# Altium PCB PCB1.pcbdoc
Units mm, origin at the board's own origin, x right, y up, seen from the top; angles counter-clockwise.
Board outline 97 x 97 mm, 2 copper layers (Top Layer, Bottom Layer), stack 1.58 mm thick; 71 components, 12 nets, 142 pads, 0 vias.
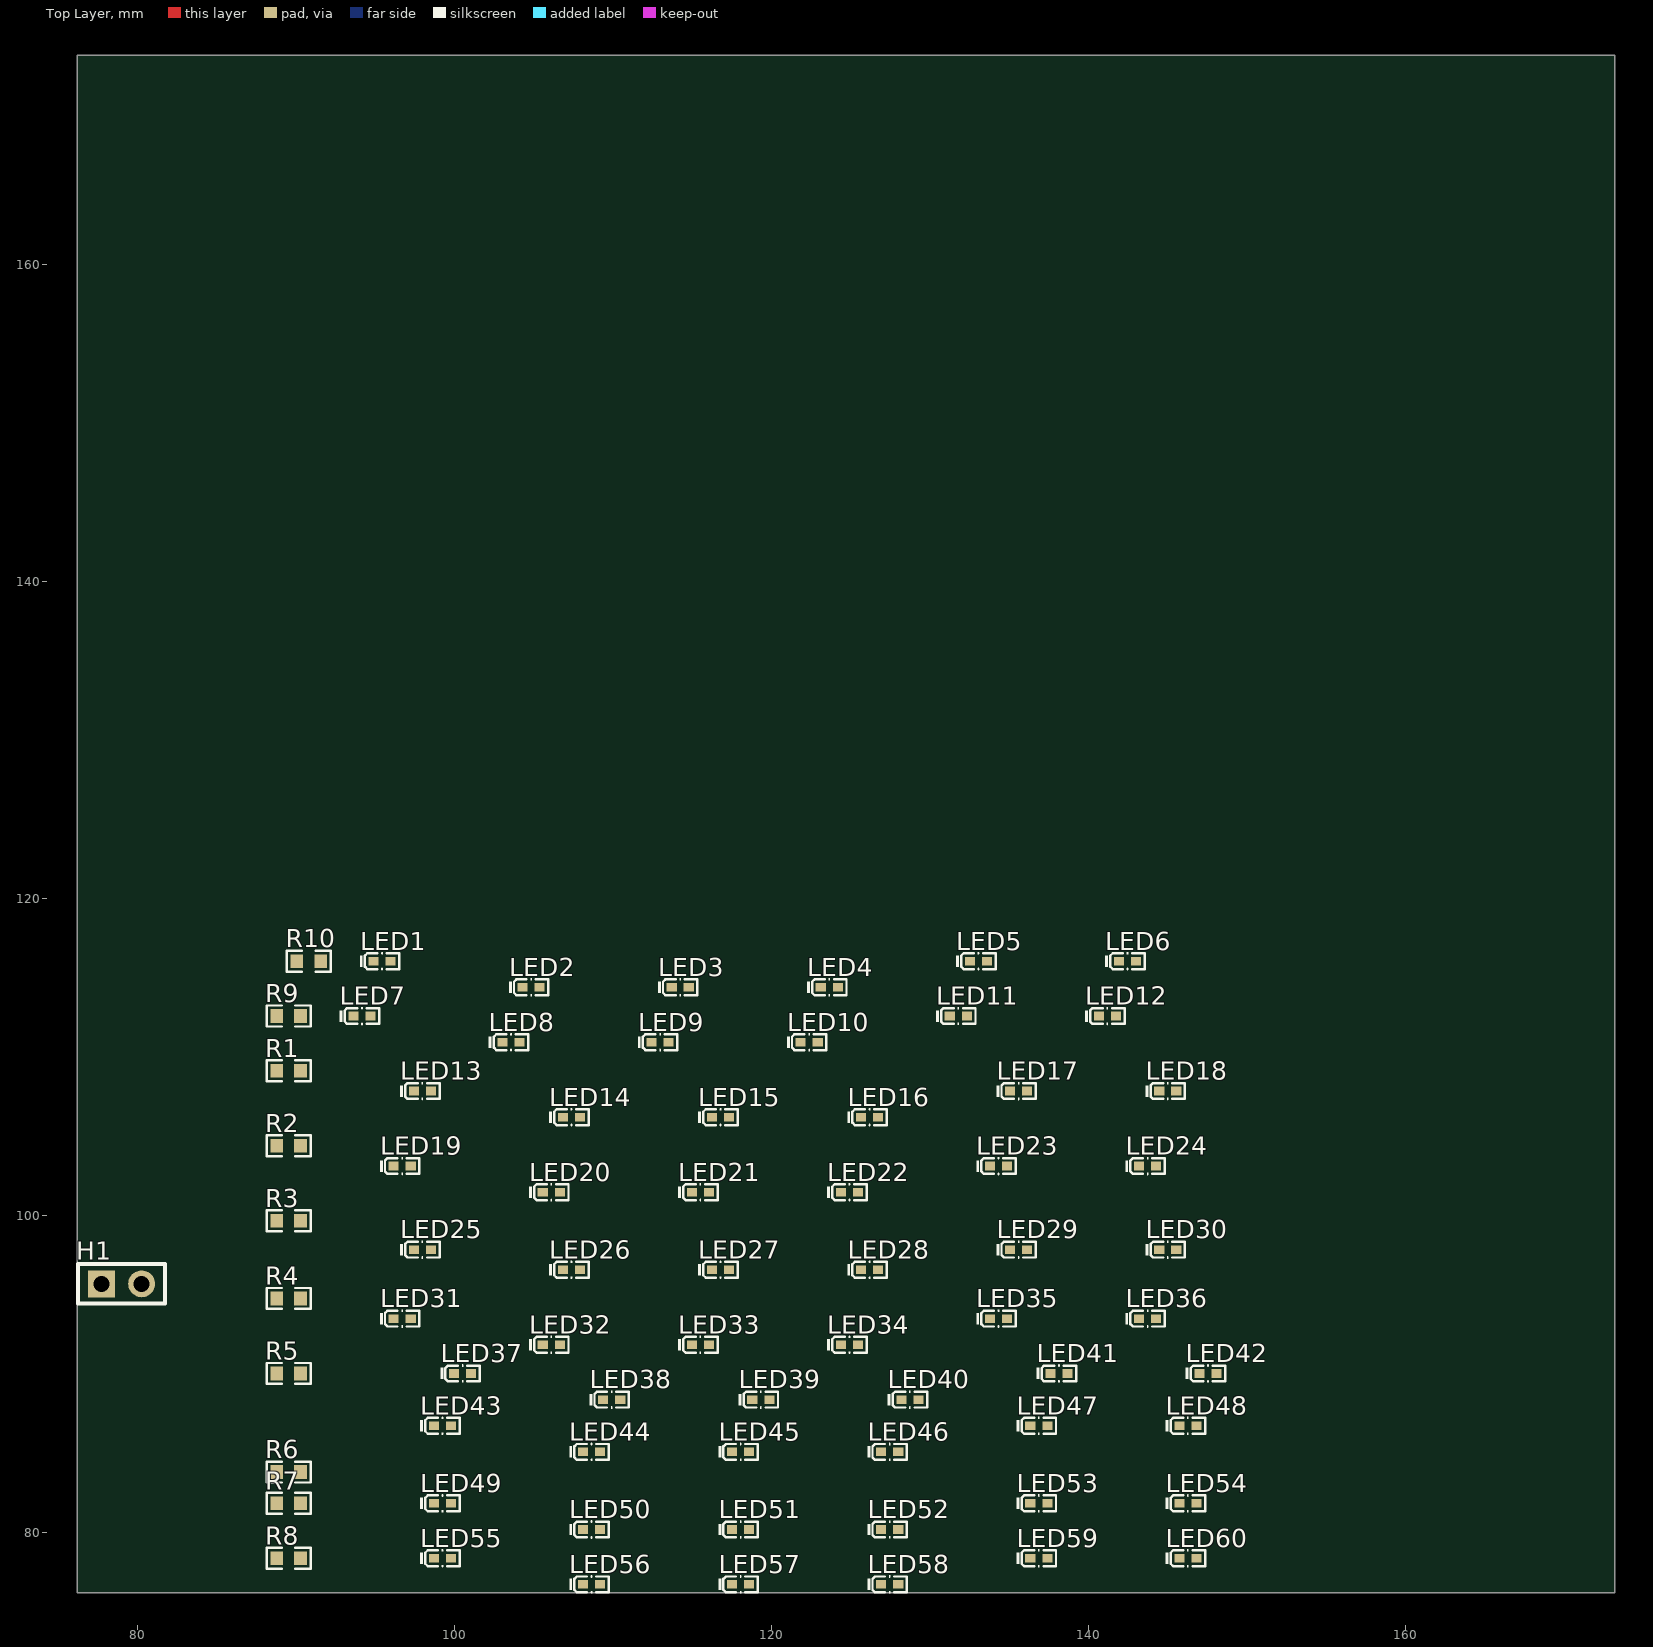
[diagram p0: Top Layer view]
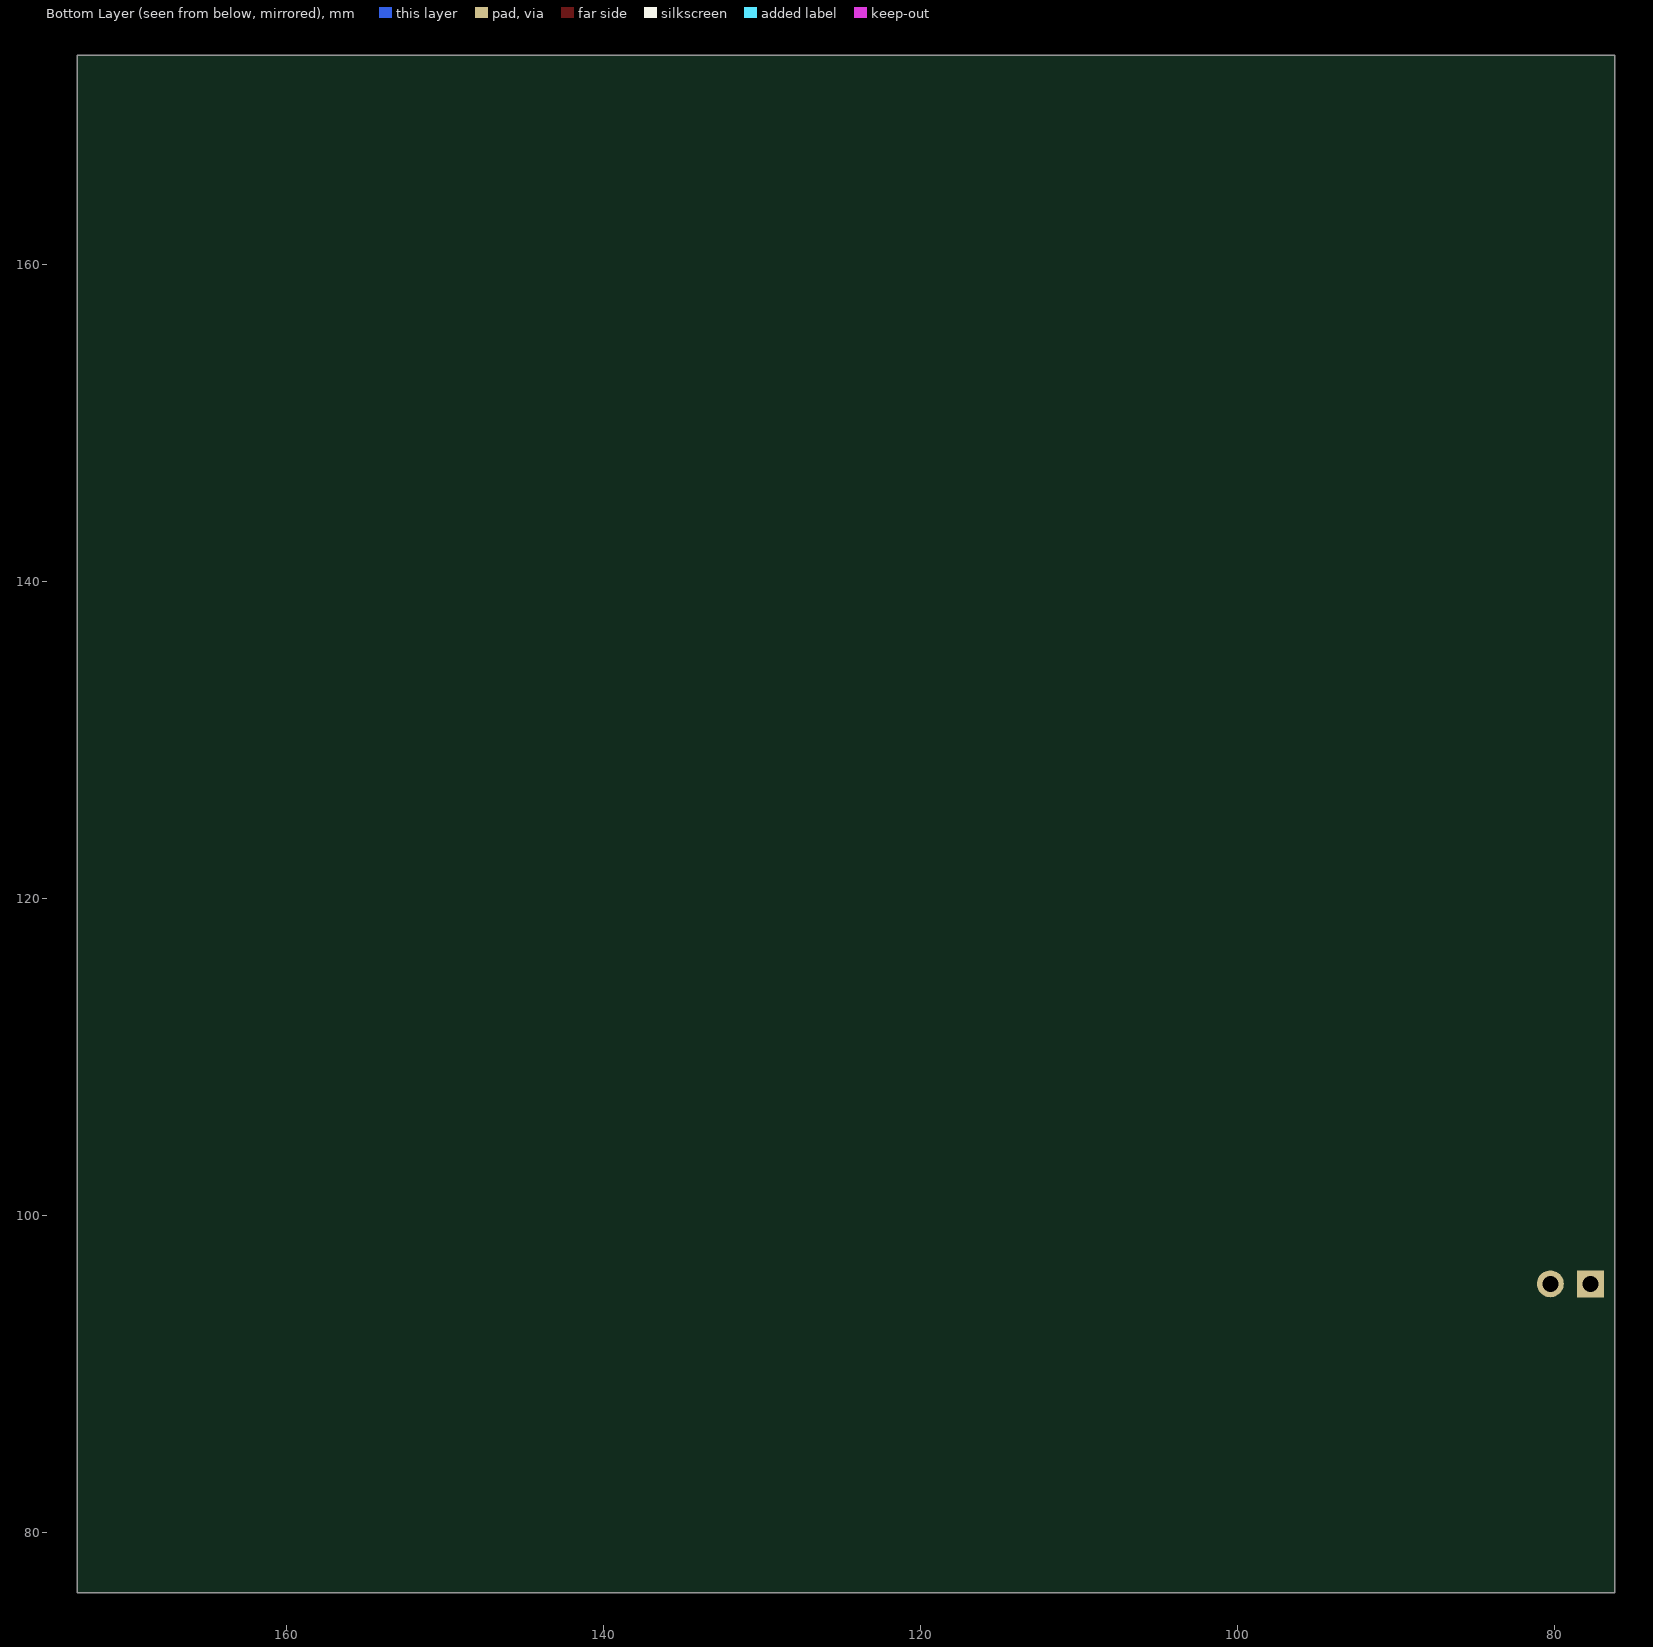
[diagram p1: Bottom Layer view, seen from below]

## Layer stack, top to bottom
Top Solder Mask Layer: solder mask 0.01, Dk 3.3
Top Layer: signal copper 0.035
Dielectric1: surface 1.51, FR4, Dk 4.5
Bottom Layer: signal copper 0.035
Bottom Solder Mask Layer: solder mask 0.01, Dk 3.3

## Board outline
76.2,173.2 76.2,76.2 173.2,76.2 173.2,173.2

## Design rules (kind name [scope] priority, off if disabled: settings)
BoardOutlineClearance copperThickness1oz [All] p0: genericclearance=0.254 ignorepadtopadclearanceinfootprint=FALSE except(0: Arc-SplitContinuation Track-SplitContinuation SMDPad-SplitContinuation THPad-SplitContinuation Via-SplitContinuation Fill-SplitContinuation Poly-SplitContinuation Region-SplitContinuation Text-SplitContinuation)
BoardOutlineClearance copperThickness2oz [All] p0: genericclearance=0.254 ignorepadtopadclearanceinfootprint=FALSE except(0: Arc-SplitContinuation Track-SplitContinuation SMDPad-SplitContinuation THPad-SplitContinuation Via-SplitContinuation Fill-SplitContinuation Poly-SplitContinuation Region-SplitContinuation Text-SplitContinuation)
BoardOutlineClearance otherClearance [All] p0: genericclearance=0.254 ignorepadtopadclearanceinfootprint=FALSE except(0: Arc-SplitContinuation Track-SplitContinuation SMDPad-SplitContinuation THPad-SplitContinuation Via-SplitContinuation Fill-SplitContinuation Poly-SplitContinuation Region-SplitContinuation Text-SplitContinuation)
Clearance copperThickness1oz [All] p1: gap=0.178 ignorepadtopadclearanceinfootprint=FALSE
Clearance copperThickness2oz [All] p1: gap=0.178 ignorepadtopadclearanceinfootprint=FALSE
Clearance otherClearance [All] p1: gap=0.178 ignorepadtopadclearanceinfootprint=FALSE
DiffPairsRouting differentialPair [All] p1: maxuncoupledlength=10 minlimit=6 maxlimit=Infinity mostfreqgap=6 toplayer_minwidth=5 toplayer_prefwidth=10 toplayer_maxwidth=100 bottomlayer_minwidth=5 bottomlayer_prefwidth=10 bottomlayer_maxwidth=100
PasteMaskExpansion pasteMaskExpansion [All] p1: expansion=0
PlaneConnect innerPlane [All] p1: planeconnectstyle=Relief reliefexpansion=0.508 reliefentries=4 reliefconductorwidth=0.254 reliefairgap=0.254
PolygonConnect copperRegion [All] p1: connectstyle=Relief reliefentries=4 reliefconductorwidth=10 polygonreliefangle="90 Angle" airgapwidth=10
RoutingVias viaSize [All] p1: viastyle="Through Hole" holewidth=12.0078 minholewidth=11.811 maxholewidth=248.0314 width=12.0078 minwidth=11.811 maxwidth=248.0314
SolderMaskExpansion solderMaskExpansion [IsVia] p1: useseparateexpansions=TRUE expansion=-1000 expansionbottom=-1000
SolderMaskExpansion solderMaskExpansion [All] p2: useseparateexpansions=TRUE expansion=2 expansionbottom=2
Width copperThickness1oz [All] p1: maxlimit=100 minlimit=5 preferedwidth=10
Width copperThickness2oz [All] p1: maxlimit=100 minlimit=8 preferedwidth=10

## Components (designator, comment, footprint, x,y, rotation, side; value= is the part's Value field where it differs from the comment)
H1 "" HDR-TH_2P-P2.54-V-F 79,95.694 r0 top
LED1 "" LED0402-RD_YELLOW 95.437,116.049 r0 top
LED2 "" LED0402-RD_YELLOW 104.841,114.4 r0 top
LED3 "" LED0402-RD_YELLOW 114.244,114.4 r0 top
LED4 "" LED0402-RD_YELLOW 123.648,114.4 r0 top
LED5 "" LED0402-RD_YELLOW 133.052,116.049 r0 top
LED6 "" LED0402-RD_YELLOW 142.455,116.049 r0 top
LED7 "" LED0402-RD_YELLOW 94.167,112.588 r0 top
LED8 "" LED0402-RD_YELLOW 103.571,110.938 r0 top
LED9 "" LED0402-RD_YELLOW 112.974,110.938 r0 top
LED10 "" LED0402-RD_YELLOW 122.378,110.938 r0 top
LED11 "" LED0402-RD_YELLOW 131.782,112.588 r0 top
LED12 "" LED0402-RD_YELLOW 141.185,112.588 r0 top
LED13 "" LED0402-RD_YELLOW 97.977,107.857 r0 top
LED14 "" LED0402-RD_YELLOW 107.381,106.207 r0 top
LED15 "" LED0402-RD_YELLOW 116.784,106.207 r0 top
LED16 "" LED0402-RD_YELLOW 126.188,106.207 r0 top
LED17 "" LED0402-RD_YELLOW 135.592,107.857 r0 top
LED18 "" LED0402-RD_YELLOW 144.995,107.857 r0 top
LED19 "" LED0402-RD_YELLOW 96.707,103.126 r0 top
LED20 "" LED0402-RD_YELLOW 106.111,101.476 r0 top
LED21 "" LED0402-RD_YELLOW 115.514,101.476 r0 top
LED22 "" LED0402-RD_YELLOW 124.918,101.476 r0 top
LED23 "" LED0402-RD_YELLOW 134.322,103.126 r0 top
LED24 "" LED0402-RD_YELLOW 143.725,103.126 r0 top
LED25 "" LED0402-RD_YELLOW 97.977,97.853 r0 top
LED26 "" LED0402-RD_YELLOW 107.381,96.583 r0 top
LED27 "" LED0402-RD_YELLOW 116.784,96.583 r0 top
LED28 "" LED0402-RD_YELLOW 126.188,96.583 r0 top
LED29 "" LED0402-RD_YELLOW 135.592,97.853 r0 top
LED30 "" LED0402-RD_YELLOW 144.995,97.853 r0 top
LED31 "" LED0402-RD_YELLOW 96.707,93.501 r0 top
LED32 "" LED0402-RD_YELLOW 106.111,91.852 r0 top
LED33 "" LED0402-RD_YELLOW 115.514,91.852 r0 top
LED34 "" LED0402-RD_YELLOW 124.918,91.852 r0 top
LED35 "" LED0402-RD_YELLOW 134.322,93.501 r0 top
LED36 "" LED0402-RD_YELLOW 143.725,93.501 r0 top
LED37 "" LED0402-RD_YELLOW 100.517,90.04 r0 top
LED38 "" LED0402-RD_YELLOW 109.921,88.39 r0 top
LED39 "" LED0402-RD_YELLOW 119.324,88.39 r0 top
LED40 "" LED0402-RD_YELLOW 128.728,88.39 r0 top
LED41 "" LED0402-RD_YELLOW 138.132,90.04 r0 top
LED42 "" LED0402-RD_YELLOW 147.535,90.04 r0 top
LED43 "" LED0402-RD_YELLOW 99.247,86.741 r0 top
LED44 "" LED0402-RD_YELLOW 108.651,85.091 r0 top
LED45 "" LED0402-RD_YELLOW 118.054,85.091 r0 top
LED46 "" LED0402-RD_YELLOW 127.458,85.091 r0 top
LED47 "" LED0402-RD_YELLOW 136.862,86.741 r0 top
LED48 "" LED0402-RD_YELLOW 146.265,86.741 r0 top
LED49 "" LED0402-RD_YELLOW 99.247,81.848 r0 top
LED50 "" LED0402-RD_YELLOW 108.651,80.198 r0 top
LED51 "" LED0402-RD_YELLOW 118.054,80.198 r0 top
LED52 "" LED0402-RD_YELLOW 127.458,80.198 r0 top
LED53 "" LED0402-RD_YELLOW 136.862,81.848 r0 top
LED54 "" LED0402-RD_YELLOW 146.265,81.848 r0 top
LED55 "" LED0402-RD_YELLOW 99.247,78.386 r0 top
LED56 "" LED0402-RD_YELLOW 108.651,76.737 r0 top
LED57 "" LED0402-RD_YELLOW 118.054,76.737 r0 top
LED58 "" LED0402-RD_YELLOW 127.458,76.737 r0 top
LED59 "" LED0402-RD_YELLOW 136.862,78.386 r0 top
LED60 "" LED0402-RD_YELLOW 146.265,78.386 r0 top
R1 "10K" R0603 89.543,109.127 r0 top
R2 "10K" R0603 89.543,104.396 r0 top
R3 "10K" R0603 89.543,99.664 r0 top
R4 "10K" R0603 89.543,94.771 r0 top
R5 "10K" R0603 89.543,90.04 r0 top
R6 "10K" R0603 89.543,83.821 r0 top
R7 "10K" R0603 89.543,81.848 r0 top
R8 "10K" R0603 89.543,78.386 r0 top
R9 "10K" R0603 89.543,112.588 r0 top
R10 "10K" R0603 90.813,116.049 r0 top

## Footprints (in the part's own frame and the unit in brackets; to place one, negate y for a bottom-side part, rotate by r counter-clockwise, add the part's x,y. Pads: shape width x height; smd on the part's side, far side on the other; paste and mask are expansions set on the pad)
HDR-TH_2P-P2.54-V-F [mm]
  rect 1.7x1.7 hole 1: 1(-1.27,0)
  round 1.7 hole 1: 2(1.27,0)
  silkscreen extent -2.74,-1.25 2.74,1.25
LED0402-RD_YELLOW [mm]
  rect 0.636x0.54 smd paste-100 mask+0.051: 1(-0.538,0) 2(0.538,0)
  silkscreen extent -1.39,-0.54 1.09,0.54
R0603 [mm]
  rect 0.806x0.864 smd paste-100 mask+0.051: 1(-0.753,0) 2(0.753,0)
  silkscreen extent -1.39,-0.66 1.39,0.66

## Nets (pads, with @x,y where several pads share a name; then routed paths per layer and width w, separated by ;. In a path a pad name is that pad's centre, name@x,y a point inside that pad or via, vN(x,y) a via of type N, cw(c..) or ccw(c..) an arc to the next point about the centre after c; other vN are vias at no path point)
$1N1: H1.1 R1.1 R2.1 R3.1 R4.1 R5.1 R6.1 R7.1 R8.1 R9.1 R10.1
$1N2: LED1.1 LED2.1 LED3.1 LED4.1 LED5.1 LED6.1 R10.2
$1N3: H1.2 LED1.2 LED2.2 LED3.2 LED4.2 LED5.2 LED6.2 LED7.2 LED8.2 LED9.2 LED10.2 LED11.2 LED12.2 LED13.2 LED14.2 LED15.2 LED16.2 LED17.2 LED18.2 LED19.2 LED20.2 LED21.2 LED22.2 LED23.2 LED24.2 LED25.2 LED26.2 LED27.2 LED28.2 LED29.2 LED30.2 LED31.2 LED32.2 LED33.2 LED34.2 LED35.2 LED36.2 LED37.2 LED38.2 LED39.2 LED40.2 LED41.2 LED42.2 LED43.2 LED44.2 LED45.2 LED46.2 LED47.2 LED48.2 LED49.2 LED50.2 LED51.2 LED52.2 LED53.2 LED54.2 LED55.2 LED56.2 LED57.2 LED58.2 LED59.2 LED60.2
$1N5: LED7.1 LED8.1 LED9.1 LED10.1 LED11.1 LED12.1 R9.2
$1N8: LED19.1 LED20.1 LED21.1 LED22.1 LED23.1 LED24.1 R2.2
$1N9: LED13.1 LED14.1 LED15.1 LED16.1 LED17.1 LED18.1 R1.2
$1N14: LED37.1 LED38.1 LED39.1 LED40.1 LED41.1 LED42.1 R5.2
$1N15: LED31.1 LED32.1 LED33.1 LED34.1 LED35.1 LED36.1 R4.2
$1N16: LED25.1 LED26.1 LED27.1 LED28.1 LED29.1 LED30.1 R3.2
$1N18: LED43.1 LED44.1 LED45.1 LED46.1 LED47.1 LED48.1 R6.2
$1N20: LED49.1 LED50.1 LED51.1 LED52.1 LED53.1 LED54.1 R7.2
$1N22: LED55.1 LED56.1 LED57.1 LED58.1 LED59.1 LED60.1 R8.2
